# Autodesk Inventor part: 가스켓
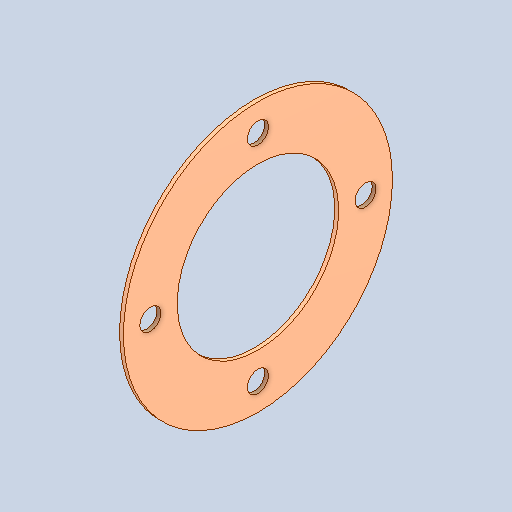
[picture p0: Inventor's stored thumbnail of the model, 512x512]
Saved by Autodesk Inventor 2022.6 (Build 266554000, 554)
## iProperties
Created: 2024-09
Part Number: 가스켓
Material: 스테인리스스틸
Document SubType Name: Modeling
Designer: Class 001
Density: 8 g/cm^3
Appearance: 기본값
Author: jhkim
Sending System: Autodesk Inventor 2025
Preprocessor: ST-DEVELOPER v20
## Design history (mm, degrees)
feature "솔리드1"
node "솔리드2"
